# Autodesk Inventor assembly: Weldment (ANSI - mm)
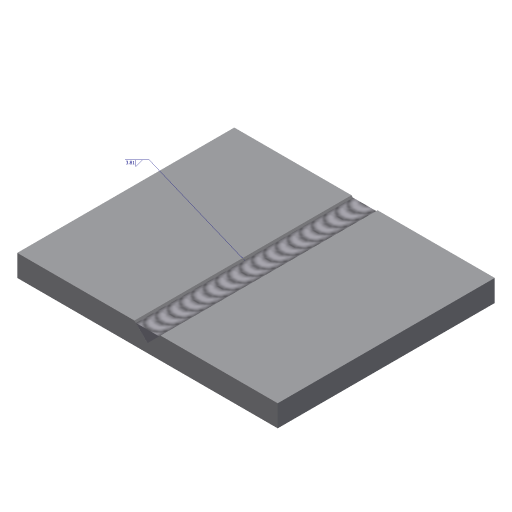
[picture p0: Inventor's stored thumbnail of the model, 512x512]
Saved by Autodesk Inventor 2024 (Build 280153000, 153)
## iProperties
Length Units: 11269
Angle Units: 11283
Time Units: 11279
Mass Units: 11290
Length Display Precision: 3
Angle Display Precision: 2
Part Number: Weldment (ANSI - mm)
Document SubType Name: Weldment
Created: 2002-06
Designer: smithga
Part Number: fig 16-6
Created: 2003-01
Designer: Owner
Control State: 0
Master: False
Shininess: 64.0
Angle Units: 11279
Time Units: 11290
Mass Units: 11283
Compacted: True
Density: 0.0
Volumn: 0.0
Area: 0.0
PropertySet Name: Model Information
Author: Owner
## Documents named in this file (2)
- D:\PROJECTS\Project 2023\RESOURCES INVENTOR 2024\RESOURCES INVENTOR 2024\Inventor_2023_Part\Inventor_2024_Part\c16_Inv_2024_prt\fig 16-6\fig 16-6.iam
- D:\PROJECTS\Project 2023\RESOURCES INVENTOR 2024\RESOURCES INVENTOR 2024\Inventor_2023_Part\Inventor_2024_Part\c16_Inv_2024_prt\fig 16-6\Part1.ipt
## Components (2 placed, 1 different names)
1. Part1:1 — Mate:1, Flush:1, Flush:2
2. Part1:2 — Mate:1, Flush:1, Flush:2
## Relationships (3: Flush 2, Mate 1)
- Mate:1: Part1:1 ↔ Part1:2
- Flush:1: Part1:1 ↔ Part1:2
- Flush:2: Part1:1 ↔ Part1:2
